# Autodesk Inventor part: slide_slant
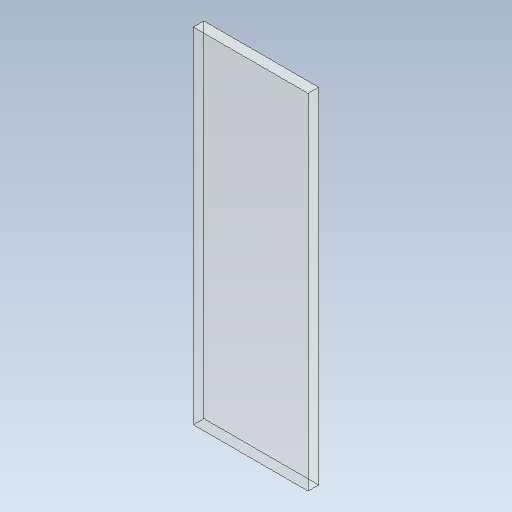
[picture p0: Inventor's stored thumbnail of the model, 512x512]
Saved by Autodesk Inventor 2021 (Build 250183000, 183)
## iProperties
Created: 2026-10
Part Number: slide_slant
Material: Generic
Document SubType Name: Modeling
Designer: alolo
Density: 1 g/cm^3
Appearance: Clear
Author: alolo
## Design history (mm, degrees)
sketch "Sketch1"
  geometry: L1 (0, 0)-(65, 0); L2 (65, 0)-(65, 195); L3 (65, 195)-(0, 195); L4 (0, 195)-(0, 0)
  constraints: 8 end point, 2 parallel, 1 horizontal, 1 perpendicular
  dimensions: "d0" = 65 distance of L3.end L2.end (= slide_width); "d1" = 195 distance of L2.end L1.end (= slide_length)
extrude "Extrusion1" new body sketch "Sketch1" distance "d2" = 6 (= aclyric_thickness); taper "d3" = 0 deg
body "Solid1"
other parameters: "slide_length" = 195 [user parameter; used in 1 equation term], "slide_angle" = 7 deg [user parameter], "slide_width" = 65 [user parameter; used in 1 equation term], "wood_thickness" = 5 [user parameter], "aclyric_thickness" = 6 [user parameter; used in 1 equation term]
